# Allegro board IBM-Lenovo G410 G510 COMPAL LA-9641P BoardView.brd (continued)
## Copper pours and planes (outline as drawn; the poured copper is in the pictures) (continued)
B+ on TOP (solid shape): 112.19,29.18 112.19,26.91 112,26.72 110.73,26.72 110.47,26.97 110.47,29.11 110.71,29.35 112.02,29.35
B+ on TOP (solid shape): 178.96,138.74 178.96,133.74 177.59,132.37 177.59,130.35 177.08,129.84 175.05,129.84 174.86,130.03 174.86,132.27 176.21,133.63 176.21,136.54 174.89,137.86 174.89,138.95 175.2,139.26 178.45,139.26
B+ on TOP (solid shape): 192.32,62.08 192.32,60.58 192.17,60.44 191.85,60.44 191.8,60.49 191.8,60.99 191.77,61.02 191.31,61.02 191.29,61 191.29,60.5 191.23,60.44 190.95,60.44 190.9,60.5 190.9,62.09 191.03,62.22 192.18,62.22
B+ on TOP (solid shape): 167.15,177.75 167.15,175.29 166.63,174.77 165.46,174.77 163.77,176.46 148.02,176.46 147.6,176.88 143.45,176.88 143.03,176.46 137.48,176.46 137.34,176.59 127.75,176.59 127.62,176.46 110.86,176.46 110.17,175.77 108.75,175.77 108.32,176.2 108.32,177.97 108.62,178.27 166.63,178.27
B+ on TOP (solid shape): 178.77,162.87 178.77,161.29 179.32,160.74 181.27,160.74 181.38,160.63 181.38,159.95 181.32,159.88 179.91,159.88 179.9,159.89 179.86,159.89 179.62,159.65 179.62,159.36 179.91,159.08 181.35,159.08 181.39,159.04 181.39,158.54 181.26,158.42 180.74,158.42 180.61,158.29 180.61,155.45 180.44,155.29 178.7,155.29 178.58,155.4 177.7,155.4 176.71,156.4 176.71,160.43 176.11,161.03 175.64,161.03 175.39,161.28 175.39,162.88 175.64,163.12 178.52,163.12
B+ on BOTTOM (solid shape): 62.08,3.48 62.08,1.55 61.83,1.29 59.34,1.29 59.18,1.45 59.18,3.46 59.45,3.73 61.84,3.73
B+ on BOTTOM (solid shape): 81.51,136.95 81.51,135.36 79.55,133.39 77.58,133.39 75.07,135.89 75.07,137.02 77.38,139.32 79.14,139.32
B+ on BOTTOM (solid shape): 93.4,4.53 93.4,1.54 93.21,1.36 92.03,1.36 91.84,1.55 91.84,4.56 92.01,4.73 93.19,4.73
B+ on BOTTOM (solid shape): 191.46,8.8 191.46,6.42 191.24,6.21 190.24,6.21 190.05,6.4 190.05,8.8 190.29,9.04 191.23,9.04
B+ on BOTTOM (solid shape): 96.86,153.09 96.85,153.08 96.85,152.64 96.87,152.63 96.87,151.99 96.86,151.99 96.86,150.67 96.68,150.49 95.79,150.49 95.57,150.71 95.57,153.11 95.72,153.26 96.69,153.26
B+ on BOTTOM (solid shape): 181.7,160.42 181.7,159.17 181.69,159.09 181.7,159.02 181.7,156.95 181.45,156.7 176.95,156.7 176.66,156.99 176.66,160.51 176.88,160.73 181.39,160.73
B+ on BOTTOM (solid shape): 167.15,177.75 167.15,175.29 166.63,174.77 165.46,174.77 163.77,176.46 138.6,176.46 137.9,177.16 137.38,177.16 137.37,177.17 127.71,177.17 127.69,177.14 127.17,177.14 126.48,176.46 110.86,176.46 110.17,175.77 108.75,175.77 108.32,176.2 108.32,177.97 108.62,178.27 166.63,178.27
B+ on VCC (solid shape): outline of 12092 points within 57.77,0.88 211.43,178.48
B+ on IN2 (solid shape): outline of 209 points within 194.64,42.94 200.94,79.82
B+ on IN2 (solid shape): outline of 941 points within 76.22,135.91 167.22,178.18
B+_0.95V on TOP (solid shape): 177.77,127.83 177.77,125.78 177.62,125.63 172.57,125.63 172.44,125.75 172.44,127.09 172.54,127.19 174.32,127.19 174.88,127.75 174.88,129.03 175.08,129.22 176.38,129.22
B+_1.5V on BOTTOM (solid shape): 197.44,10.6 197.44,6.71 196.93,6.2 192.47,6.2 192.3,6.37 192.3,9.36 193.59,10.64 197.4,10.64
BATT+ on TOP (solid shape): 176.93,170.39 177.47,170.39 178.29,169.57 179.22,169.57 180.05,168.73 180.05,166.3 179.8,166.04 175.74,166.04 173.04,168.74 170.63,168.74 170.55,168.82 170.55,170.27 170.34,170.48 169.96,170.48 169.74,170.26 169.74,168.75 168.76,167.78 168.76,166.78 168.55,166.57 167.83,166.57 167.73,166.67 167.73,170 167.53,170.2 167.53,171.11 167.96,171.54 175.78,171.54
BATT+ on BOTTOM (solid shape): 178.39,169.57 179.17,169.57 179.31,169.43 179.31,167.6 179.27,167.56 174.61,167.56 174.4,167.77 174.4,170.01 174.62,170.24 177.72,170.24
BOOT1_1_VGA on TOP (solid shape): 183.98,143.15 183.98,142.35 183.89,142.25 181.91,142.25 181.82,142.34 181.82,143.1 181.96,143.23 183.9,143.23
BOOT1_VGA on TOP (solid shape): 185.38,143.13 185.38,141.98 185.93,141.43 185.93,140.3 185.86,140.24 185.78,140.24 185.71,140.3 185.71,141.2 185.55,141.37 185.38,141.37 184.49,142.25 184.49,143.14 184.68,143.33 185.18,143.33
BOOT2_2_VGA on TOP (solid shape): 181.11,137.47 181.11,135.51 180.97,135.36 180.31,135.36 180.15,135.52 180.15,137.47 180.36,137.68 180.9,137.68
BOOT2_VGA on TOP (solid shape): 185.25,136.51 185.25,136.41 184.23,135.39 181.84,135.39 181.72,135.39 181.67,135.45 181.67,136.33 181.74,136.41 182.7,136.41 183.18,135.93 183.63,135.93 184.27,136.57 185.2,136.57
BQ24737VCC on TOP (solid shape): 186.92,165.78 186.92,165.67 186.18,164.93 185.76,164.93 185.61,165.09 185.61,165.58 185.9,165.87 186.82,165.87
BQ24737VCC on BOTTOM (solid shape): 184.58,166.37 184.58,165.6 184.56,165.5 184.58,165.4 184.58,165.24 184.73,165.08 185.32,165.08 185.78,165.54 186.02,165.54 186.14,165.42 186.14,163.48 185.78,163.12 183.86,163.12 183.43,163.55 183.43,166.24 183.59,166.39 183.64,166.4 183.68,166.41 184.53,166.41
BQ24737VDD on TOP (solid shape): 186.18,167.89 186.81,167.89 186.92,167.78 186.92,167.68 186.81,167.58 185.31,167.58 184.39,168.5 183.06,168.5 182.86,168.69 182.86,170.07 183.06,170.26 183.81,170.26
BST_1.05VSP on TOP (solid shape): 101.43,36.15 101.43,33.96 102.02,33.36 102.34,33.36 102.42,33.28 102.42,33.15 102.34,33.08 101.15,33.08 100.36,33.87 100.36,36.1 100.51,36.25 101.33,36.25
BST_1.35V on TOP (solid shape): 37.21,8.41 37.21,7.4 37.05,7.24 36.46,7.24 35.88,7.82 33.91,7.82 33.85,7.88 33.85,8.03 33.88,8.06 35.26,8.06 35.46,8.26 35.67,8.26 35.92,8.51 37.1,8.51
BST_1.35V-1 on TOP (solid shape): 38.54,8.22 38.54,6.52 38.44,6.42 37.54,6.42 37.43,6.54 37.43,8.23 37.56,8.36 38.4,8.36
BST_3V on TOP (solid shape): 65.01,6.95 65.01,5.61 65.01,5.61 65.01,5.14 65.34,4.81 65.43,4.81 65.52,4.71 65.52,3.69 65.44,3.6 64.75,3.6 64.51,3.85 64.51,6.94 64.63,7.06 64.9,7.06
BST_3V_1 on TOP (solid shape): 67.99,4.78 67.99,3.84 67.9,3.76 66.24,3.76 66.2,3.8 66.2,4.78 66.26,4.85 67.92,4.85
BST_5V on TOP (solid shape): 99.97,7.63 99.97,7.08 99.82,6.93 98.75,6.93 98.19,6.37 97.11,6.37 97.02,6.46 97.02,7.04 97.12,7.15 98,7.15 98.15,7.3 98.15,7.62 98.3,7.77 99.82,7.77
BST_5V on BOTTOM (solid shape): 99.99,7.57 99.99,7.33 100.44,6.89 100.44,6.52 100.34,6.43 100.15,6.43 99.4,7.19 99.4,7.6 99.54,7.74 99.82,7.74
BST_5V_1 on TOP (solid shape): 99.59,8.71 99.59,8.01 99.49,7.91 98.17,7.91 98.02,7.76 97.15,7.76 97.08,7.84 97.08,8.75 97.2,8.88 99.43,8.88
BST_CHG on TOP (solid shape): 184.39,168.14 185.15,167.38 186.83,167.38 186.93,167.27 186.93,167.17 186.86,167.1 185.6,167.1 185.59,167.11 185.47,167.12 185.36,167.11 185.35,167.1 184.92,167.1 184.81,167.12 184.7,167.1 183.69,167.1 183.69,167.11 183.28,167 183.26,166.58 183.26,165.51 183.18,165.43 182.25,165.43 182.15,165.53 182.15,165.67 182.15,167.84 182.46,168.14 184.09,168.14
BST_CPU_PHASE1 on BOTTOM (solid shape): 28.2,124.97 28.2,123.88 28.02,123.7 27.37,123.7 26.49,122.82 25.5,122.82 25.44,122.88 25.44,123.02 27.52,125.09 28.08,125.09
BST_CPU_PHASE1-1 on BOTTOM (solid shape): 29.64,124.98 29.64,123.25 29.47,123.07 28.91,123.07 28.78,123.21 28.78,124.96 28.95,125.14 29.48,125.14
BSTA2 on TOP (solid shape): 29.6,94.37 29.6,93.72 29.43,93.55 29.43,92.86 29.38,92.81 28.65,92.81 28.57,92.89 28.57,94.32 28.7,94.46 29.51,94.46
BSTA2_1 on TOP (solid shape): 31.97,94.59 31.97,93.85 31.88,93.75 31.1,93.75 30.91,93.56 30.25,93.56 30.14,93.67 30.14,94.66 30.24,94.76 31.8,94.76
CHASSIS1_GND on TOP (solid shape): 20.8,79.13 20.8,78.27 20.6,78.07 19.56,78.07 19.4,78.22 19.4,79.12 19.55,79.27 20.66,79.27
CHASSIS1_GND on TOP (solid shape): 14.86,80.86 14.86,79.73 14.69,79.56 12.87,79.56 12.77,79.66 12.77,80.86 12.96,81.05 14.67,81.05
CHASSIS1_GND on TOP (solid shape): 21.01,86.32 21.01,85.47 21,85.46 21,83.75 20.8,83.54 19.44,83.54 19.34,83.64 19.34,86.25 19.56,86.47 20.87,86.47
CHASSIS1_GND on TOP (solid shape): 14.11,99.99 14.11,97.63 16.5,95.23 21.76,95.23 23.39,93.61 23.39,88.4 23.11,88.12 20.67,88.12 20.43,88.36 20.43,92.82 19.54,93.71 14.93,93.71 12.04,96.6 12.04,98.83 10.68,100.19 8.8,100.19 8.28,99.67 7.94,99.67 7.78,99.84 7.78,101.26 8.45,101.92 12.17,101.92
CHASSIS1_GND on GND: 15.03,75.85 13.06,77.82 9.45,77.82 9.3,77.67 9.3,77.61 8.04,78.03 7.11,77.07 1.1,77.07 0.57,77.28 0.36,77.81 0.36,80.29 0.57,80.81 1.1,81.03 8.47,81.03 10.59,80.4 9.96,82.51 9.96,96.66 10.59,98.77 8.47,98.14 1,98.14 0.47,98.36 0.26,98.88 0.26,101.11 0.35,101.01 5.2,101.01 5.86,101.67 11.38,101.67 12.3,100.75 12.3,95.4 10.65,93.75 10.65,85.41 11.18,84.88 12.41,84.88 14.08,86.56 14.08,90.38 14.41,90.38 19.92,84.87 19.92,77.05 18.72,75.85
CHG on TOP (solid shape): 169.75,167.63 169.75,166.13 169.95,165.94 170.31,165.94 170.56,166.18 170.56,167.6 170.64,167.69 171.34,167.69 171.53,167.51 171.53,165.25 171.07,164.8 166.55,164.8 166.38,164.97 166.38,166.23 166.56,166.41 168.66,166.41 169.02,166.77 169.02,167.65 169.06,167.7 169.68,167.7
CHG on BOTTOM (solid shape): 172.68,170.82 172.68,165.25 172.19,164.75 166.55,164.75 166.35,164.95 166.35,169.21 168.13,170.99 172.51,170.99
CHG_B+ on TOP (solid shape): 182.02,167.74 182.02,165.72 179.85,163.55 175.12,163.55 174.81,163.23 174.81,160.79 175.01,160.59 176.04,160.59 176.28,160.34 176.28,158.8 176.09,158.61 171.76,158.61 171.38,158.99 171.38,160.45 171.69,160.76 173.03,160.76 173.53,161.26 173.53,166.19 173.6,166.26 174.91,166.26 175.4,165.77 179.98,165.77 180.53,166.32 180.53,167.68 180.64,167.79 181.97,167.79
CHG_B+ on BOTTOM (solid shape): 181.87,165.74 181.87,163.36 181.42,162.91 175.8,162.91 175.2,163.51 175.2,165.66 175.49,165.96 181.66,165.96
CPU_B+ on TOP (solid shape): 75.63,132.46 75.63,131.6 74.57,130.54 73.35,130.54 71.14,132.75 71.14,133.58 72.33,134.77 73.31,134.77
CPU_B+ on TOP (solid shape): 44.7,131.26 44.7,122.4 44.36,122.07 43.62,122.07 40.79,119.24 40.79,114.94 36.11,110.26 36.11,104.92 36.06,104.87 36.13,104.81 36.13,100.58 35.92,100.38 30.63,100.38 30.37,100.12 29.26,100.12 28.8,99.67 28.8,95.73 28.71,95.64 27.72,95.64 26.29,94.21 25.29,94.21 25.22,94.28 25.22,95.79 25.63,96.21 25.63,104.21 26.12,104.7 30.46,104.7 30.84,105.08 30.96,105.08 30.91,105.12 30.91,109.48 38.51,117.07 38.51,120.71 39.98,122.18 39.98,126.6 39.07,127.51 35.72,127.51 33.48,125.27 32.19,125.27 32.04,125.42 32.04,128.8 31.82,129.01 30.27,129.01 29.52,128.27 27.95,128.27 27.79,128.43 27.79,129.42 28.06,129.69 35.58,129.69 37.52,131.63 44.33,131.63
CPU_B+ on BOTTOM (solid shape): 27.41,100.47 27.41,94.54 26.91,94.03 23.92,94.03 23.48,94.47 23.48,100.5 23.67,100.7 27.19,100.7
CPU_B+ on VCC (solid shape): outline of 560 points within 36.62,122.59 74.86,139.64
DH_1.05VSP on TOP (solid shape): 103.29,36.11 103.29,33.53 103.21,33.44 103.07,33.44 102.99,33.52 102.99,34.69 102.76,34.93 102.76,36.11 102.85,36.2 103.19,36.2
DH_1.05VSP on TOP (solid shape): 110.38,33.45 110.45,33.45 110.64,33.26 110.64,32.85 110.64,32.84 110.64,32.29 110.36,32.01 109.02,32.01 108.89,32.14 108.89,32.15 108.71,32.33 108.71,33.26 108.91,33.45 110.37,33.45
DH_1.05VSP on IN1 (solid shape): 103.38,37.24 103.38,34.86 103.22,34.7 102.85,34.7 102.58,34.97 102.58,37.28 102.76,37.46 103.16,37.46
DH_1.05VSP on IN1 (solid shape): 110.36,33.07 110.36,32.13 110.19,31.97 109.2,31.97 109.05,32.11 109.05,32.99 109.36,33.3 110.12,33.3
DH_CHG on TOP (solid shape): 176.75,156 176.75,153.67 176.47,153.4 175.66,153.4 175.43,153.63 175.43,156.1 175.6,156.28 176.46,156.28
DH_CHG on TOP (solid shape): 183.66,164.93 184.37,164.93 184.41,164.9 184.41,164.26 184.38,164.23 183.43,164.23 183.32,164.35 183.32,164.72 183.22,164.82 182.25,164.82 182.17,164.91 182.17,165.18 182.26,165.28 183.32,165.28
DH_CHG on IN2 (solid shape): 177.83,155.66 177.83,155.02 177.59,154.78 175.88,154.78 175.56,155.11 175.56,155.89 175.83,156.15 177.33,156.15
DH_CHG on IN2 (solid shape): 183.3,165.17 183.3,164.04 183.13,163.86 182.27,163.86 182.1,164.03 182.1,165.12 182.28,165.3 183.18,165.3
DH_CHG-1 on TOP (solid shape): 185.72,166.87 186.82,166.87 186.92,166.78 186.92,166.68 186.84,166.6 185.57,166.6 185.42,166.46 185.04,166.46 184.44,165.86 184.44,165.69 184.39,165.64 183.54,165.64 183.5,165.68 183.5,166.29 183.55,166.33 183.7,166.33 184.34,166.97 185.62,166.97
DISCHG_G on TOP (solid shape): 180.75,162.69 180.75,161.75 180.19,161.19 179.48,161.19 179.28,161.39 179.28,162.94 179.47,163.13 180.32,163.13
DL_1.05VSP on TOP (solid shape): 118.3,44.19 118.3,44.18 118.41,44.07 118.41,42.53 118.28,42.4 116.64,42.4 116.37,42.67 116.37,43.09 117.68,44.4 118.08,44.4
DL_1.05VSP on TOP (solid shape): 104.09,35.85 104.09,34.96 103.79,34.65 103.79,33.54 103.7,33.45 103.59,33.45 103.5,33.54 103.5,34.14 103.51,34.15 103.51,35.83 103.68,36 103.95,36
DL_1.05VSP on IN2 (solid shape): 118.17,44.27 118.17,43.3 117.21,42.34 115.86,42.34 115.58,42.63 115.58,43.52 116.48,44.42 118.02,44.42
DL_1.05VSP on IN2 (solid shape): 105.56,37.27 105.56,36.36 105.36,36.15 104.62,36.15 104.15,35.68 104.15,34.96 103.98,34.79 103.7,34.79 103.51,34.98 103.51,36.95 103.91,37.36 105.47,37.36
DL_CHG on TOP (solid shape): 166.59,163.55 166.59,161.18 166.3,160.89 166.11,160.89 165.76,161.23 165.76,162.17 165.3,162.64 165.3,163.58 165.46,163.74 166.4,163.74
DL_CHG on TOP (solid shape): 187.25,168.88 187.25,168 187.16,167.92 187.07,167.92 186.7,168.29 186.27,168.29 186.12,168.44 186.12,169.36 186.24,169.48 186.65,169.48
DL_CHG on IN2 (solid shape): 167.01,163.09 167.01,161.98 166.82,161.79 166.13,161.79 165.37,162.55 165.37,163.57 165.56,163.76 166.33,163.76
DL_CHG on IN2 (solid shape): 186.7,169.37 186.7,168.49 186.49,168.27 186.29,168.27 186.11,168.44 185.11,168.44 184.91,168.64 184.91,169.41 185.07,169.57 186.51,169.57
ECAGND on TOP (solid shape): 158.46,88.89 158.46,88.38 158.46,88.38 158.46,88.32 159.2,87.59 159.2,87.08 158.83,86.71 157.73,86.71 157.51,86.92 157.51,87.65 157.01,88.15 156.95,88.15 156.69,88.41 156.69,89.01 156.79,89.11 158.24,89.11
ENLDO_3V5V on TOP (solid shape): 112.56,4.6 112.56,2.99 112.35,2.78 110.83,2.78 110.66,2.96 110.66,4.64 110.75,4.73 112.43,4.73
HG1 on TOP (solid shape): 39.25,122.87 39.25,122.25 38.7,121.7 37.42,121.7 37.23,121.88 37.23,122.06 38.22,123.05 39.08,123.05
HG1 on BOTTOM (solid shape): 28.47,123.39 28.47,123.11 28.35,122.99 27.35,122.99 26.78,122.42 25.5,122.42 25.44,122.49 25.44,122.57 25.49,122.63 26.52,122.63 27.39,123.49 27.39,123.49 27.43,123.53 28.33,123.53
HG1 on IN2 (solid shape): 38.46,123.99 38.46,121.84 38.27,121.65 37.52,121.65 37.23,121.93 37.23,122.62 36.86,122.99 27.4,122.99 27.23,123.16 27.23,123.37 27.38,123.51 30.74,123.51 31.34,124.11 38.34,124.11
HG2 on TOP (solid shape): 38.22,105.39 38.22,104.44 38.04,104.27 37.11,104.27 36.62,104.76 36.62,105.78 36.79,105.95 37.66,105.95
HG2 on TOP (solid shape): 32.94,93.39 32.94,93.13 32.81,92.99 31.94,92.99 31.77,92.83 30.88,92.83 30.82,92.89 30.82,93.01 30.9,93.09 31.48,93.09 31.93,93.54 32.8,93.54
HG2 on IN1 (solid shape): 37.89,105.78 37.89,104.06 37.54,103.71 36.84,103.71 36.56,104 36.56,105.71 36.75,105.9 37.76,105.9
HG2 on IN1 (solid shape): 34.03,94.24 34.03,93.35 33.65,92.97 31.94,92.97 31.74,93.16 31.74,93.79 31.87,93.92 32.7,93.92 33.21,94.43 33.84,94.43
HG3 on TOP (solid shape): 26.48,106.71 26.48,105.7 26.26,105.48 25.24,105.48 25.1,105.62 25.1,106.76 25.22,106.88 26.31,106.88
HG3 on BOTTOM (solid shape): 26.52,119.74 26.52,119.43 26.82,119.13 26.82,119.13 27.26,118.68 28.36,118.68 28.49,118.55 28.49,118.3 28.31,118.13 26.91,118.13 25.44,119.6 25.44,119.77 25.51,119.83 26.43,119.83
HG3 on IN2 (solid shape): 26.85,106.69 26.85,105.81 26.64,105.6 25.16,105.6 25.04,105.71 25.04,106.63 25.2,106.78 26.76,106.78
HG3 on IN2 (solid shape): 29.49,117.95 29.49,117.44 29.28,117.23 27.85,117.23 27.68,117.4 27.71,117.44 27.75,117.84 27.38,118.02 27.3,118.04 27.27,118.12 27.27,118.48 27.45,118.66 28.78,118.66
HGNDA on TOP (solid shape): 151.15,50.47 152,50.47 152.12,50.36 152.12,50.05 152.01,49.94 150.08,49.94 149.98,50.03 149.98,50.67 150.02,50.71 150.91,50.71
HGNDA on BOTTOM (solid shape): 24.34,16.71 24.34,15.93 24.2,15.8 19.74,15.8 19.21,15.26 17.2,15.26 17.02,15.44 17.02,16.19 17.69,16.86 24.19,16.86
HGNDA on BOTTOM (solid shape): 120.61,23.94 120.61,23.54 120.6,23.54 119.15,22.08 118.83,22.08 118.52,22.39 118.52,23.1 119.63,24.21 120.35,24.21
HGNDA on IN1 (solid shape): 121.52,24.69 121.52,24.28 121.51,24.28 120.06,22.83 119.74,22.83 119.43,23.14 119.43,23.85 120.54,24.96 121.26,24.96
HGNDA on IN1 (solid shape): outline of 310 points within 145.11,49.95 152.36,56.57
HGNDA on IN2 (solid shape): 17.63,16.23 17.63,15.43 17.62,15.41 17.62,15.19 17.44,15.01 16.01,15.01 15.86,15.15 15.86,16.28 16.02,16.43 17.43,16.43
HGNDB on TOP (solid shape): 152.25,49.57 152.25,49.19 152.17,49.11 150.57,49.11 150.53,49.07 150.04,49.07 150.01,49.1 150.01,49.65 150.03,49.68 152.15,49.68
HGNDB on BOTTOM (solid shape): 19.88,13.88 19.89,13.88 19.98,13.79 24.22,13.79 24.49,13.53 24.49,13.03 24.26,12.8 17.61,12.8 17,13.41 17,14.22 17.26,14.48 19.29,14.48
HGNDB on BOTTOM (solid shape): 121.34,22.31 121.34,21.9 119.87,20.43 119.36,20.43 119.23,20.56 119.23,21.19 120.65,22.61 121.04,22.61
HGNDB on IN1 (solid shape): 17.54,14.27 17.54,13.47 17.35,13.28 15.75,13.28 15.55,13.48 15.55,14.16 15.81,14.43 17.37,14.43
HGNDB on IN1 (solid shape): 122.22,23.41 122.22,22.99 120.75,21.52 120.24,21.52 120.11,21.65 120.11,22.29 121.53,23.7 121.92,23.7
HGNDB on IN1 (solid shape): 152.3,49.44 152.3,48.94 151.44,48.08 149.74,48.08 149.44,48.38 149.44,49.36 149.72,49.64 152.09,49.64
LG1 on TOP (solid shape): 29.85,121.86 29.85,121.1 30.09,120.85 31.2,120.85 31.37,120.69 31.37,120.4 31.16,120.19 29.58,120.19 28.61,121.16 28.61,121.96 28.76,122.11 29.6,122.11
LG1 on BOTTOM (solid shape): 29.88,121.96 29.88,121.58 29.7,121.4 28.73,121.4 28.51,121.62 25.5,121.62 25.44,121.68 25.44,121.77 25.5,121.83 27.51,121.83 27.57,121.89 27.57,121.89 27.76,122.07 29.76,122.07
LG2 on TOP (solid shape): 37.76,95.11 37.76,93.77 37.51,93.52 36.37,93.52 36.18,93.71 36.18,95.19 36.43,95.44 37.43,95.44
LG2 on TOP (solid shape): 31.92,91.35 33.61,91.35 33.88,91.08 33.88,90.67 33.54,90.33 31.93,90.33 31.73,90.53 31.73,90.97 31.38,91.32 30.89,91.32 30.82,91.4 30.82,91.51 30.9,91.58 31.68,91.58
LG3 on TOP (solid shape): 25.32,101.9 25.32,100.82 24.68,100.19 23.92,100.19 23.76,100.35 23.76,101.31 24.02,101.57 24.41,101.57 24.94,102.09 25.13,102.09
LG3 on BOTTOM (solid shape): 27.33,120.1 28.32,120.1 28.46,119.96 28.46,119.71 28.31,119.56 27.44,119.56 27.26,119.75 27.26,119.82 26.65,120.42 25.5,120.42 25.44,120.48 25.44,120.57 25.49,120.63 26.81,120.63
LG3 on IN2 (solid shape): 26.33,101.39 26.33,100.6 25.98,100.24 25.39,100.24 24.72,100.91 24.72,101.87 24.94,102.09 25.64,102.09
LG3 on IN2 (solid shape): 29.81,119.89 29.81,119.29 29.56,119.04 29.11,119.04 28.56,119.59 27.41,119.59 27.26,119.74 27.26,119.97 27.39,120.1 29.59,120.1
LG_1.35V on TOP (solid shape): 34.19,6.42 34.25,6.42 34.43,6.24 34.43,5.39 34.3,5.26 33.97,5.26 33.83,5.4 33.83,5.66 33.44,6.05 33.44,6.79 33.47,6.83 33.79,6.83
LG_1.35V on BOTTOM (solid shape): 38.45,7.1 38.45,6.79 38.28,6.62 37.15,6.62 36.3,5.76 34.79,5.76 34.27,5.24 34.02,5.24 33.79,5.47 33.79,5.69 33.79,5.69 33.79,6.34 34.16,6.72 36.03,6.72 36.6,7.29 38.25,7.29
LGATE1_VGA on TOP (solid shape): 184.1,139.36 185.19,139.36 185.24,139.3 185.24,139.21 185.18,139.15 183.89,139.15 183.7,139.34 182.51,139.34 182.41,139.45 182.41,139.75 182.52,139.86 183.6,139.86
LGATE1_VGA on BOTTOM (solid shape): 172.48,145.22 172.48,144.79 172.31,144.61 171.74,144.61 171.35,144.23 170.39,144.23 170.24,144.38 170.24,145.27 170.41,145.45 172.25,145.45
LGATE1_VGA on IN2 (solid shape): 173.02,145.18 173.02,144.39 172.73,144.1 170.41,144.1 170.22,144.29 170.22,145.28 170.35,145.41 172.79,145.41
LGATE1_VGA on IN2 (solid shape): 181.97,139.88 182.57,139.88 182.66,139.87 182.75,139.88 183.43,139.88 183.61,139.7 183.61,139.5 183.45,139.34 180.57,139.34 180.3,139.6 180.3,140.24 180.66,140.6 181.26,140.6
LGATE2_VGA on TOP (solid shape): 183.99,138.17 185.18,138.17 185.24,138.1 185.24,138.01 185.19,137.96 182.63,137.96 182.49,138.1 182.49,138.36 182.61,138.48 183.67,138.48
LGATE2_VGA on BOTTOM (solid shape): 171.48,137.33 172.09,137.33 172.36,137.06 172.36,136.71 172.06,136.41 170.9,136.41 170.75,136.56 170.75,137.45 170.94,137.64 171.18,137.64
LGATE2_VGA on IN2 (solid shape): 172.97,137.63 172.97,136.68 172.73,136.45 170.92,136.45 170.78,136.59 170.78,137.67 170.95,137.84 172.75,137.84
LGATE2_VGA on IN2 (solid shape): 182.68,138.52 182.77,138.53 183.29,138.53 183.34,138.53 183.55,138.53 183.7,138.37 183.7,138.11 183.56,137.98 182.43,137.98 181.85,137.4 180.62,137.4 180.47,137.54 180.47,138.53 182.59,138.53
LX_0.95V on TOP (solid shape): 171.44,127.75 171.44,126.67 171.39,126.62 170.39,126.62 169.39,125.62 168.45,125.62 168.26,125.8 168.26,127.38 168.69,127.8 171.39,127.8
LX_0.95V on BOTTOM (solid shape): 168.47,129.99 168.47,129.08 168.73,128.82 170.11,128.82 170.29,128.64 170.29,126.34 169.44,125.49 169.44,123.63 169.19,123.37 166.5,123.37 165.92,123.96 165.92,129.91 166.16,130.15 168.32,130.15
LX_1.5V on TOP (solid shape): outline of 89 points within 197.41,6.97 206.49,11.44
LX_1.5V on BOTTOM (solid shape): 199.66,10.42 200.12,10.42 200.32,10.61 202.32,10.61 202.53,10.4 202.53,7.37 202.23,7.07 199.95,7.07 199.79,7.23 199.79,9.31 199.66,9.44 198.53,9.44 198.51,9.46 198.51,10.62 198.52,10.63 199.44,10.63
LX_1.05VSP on TOP (solid shape): 102.6,36.27 102.6,35.43 102.53,35.35 102.53,34.95 102.79,34.69 102.79,33.53 102.7,33.44 102.59,33.44 101.66,34.38 101.66,36.18 101.79,36.31 102.56,36.31
LX_1.05VSP on TOP (solid shape): 113.35,45.55 113.35,43.7 113.78,43.28 113.78,39.07 112.15,37.44 112.15,34.43 111.69,33.97 108.58,33.97 108.39,34.16 108.39,45.19 109.23,46.02 112.88,46.02
LX_1.05VSP on BOTTOM (solid shape): 114.72,40.66 114.72,36.31 114.03,35.61 109.2,35.61 108.38,36.43 108.38,40.72 108.74,41.08 114.3,41.08
LX_1.05VSP on IN2 (solid shape): 102.58,35.27 102.58,34.32 102.28,34.02 101.84,34.02 101.62,34.24 101.62,35.33 101.85,35.56 102.28,35.56
LX_1.05VSP on IN2 (solid shape): 109.87,38.78 109.87,38.3 109.7,38.12 108.55,38.12 108.42,38.26 108.42,38.79 108.57,38.95 109.71,38.95
LX_1.35V on TOP (solid shape): 45.83,10.62 45.83,5.41 45.36,4.95 37.58,4.95 37.16,5.36 35.52,5.36 33.84,7.05 33.84,7.2 33.89,7.25 34.73,7.25 34.75,7.23 34.75,7.03 35.36,6.42 37.28,6.42 37.47,6.22 38.55,6.22 39.66,7.33 39.66,10.55 40.07,10.96 45.49,10.96
LX_1.35V on BOTTOM (solid shape): 45.97,10.73 45.97,7.08 46.93,6.12 49.61,6.12 49.89,5.83 49.89,3.03 49.45,2.59 46.92,2.59 46.66,2.85 46.66,4.73 45.82,5.57 44.32,5.57 43.76,5.01 43.76,2.83 43.5,2.57 39.37,2.57 38.97,2.97 38.97,10.72 39.62,11.36 45.33,11.36
LX_3V on TOP (solid shape): 73.76,13.52 73.76,4.69 72.63,3.56 68.93,3.56 68.65,3.84 68.65,5.58 69.39,6.32 69.39,7.59 69.19,7.8 66.63,7.8 66.58,7.84 66.58,8.94 68.25,8.94 71.28,11.97 71.28,13.6 71.61,13.93 73.35,13.93
LX_5V on TOP (solid shape): 106.59,6.55 106.59,5.18 106.36,4.95 103.98,4.95 103.86,5.08 103.86,6.69 104.01,6.84 106.29,6.84
LX_5V on BOTTOM (solid shape): 108.75,11.27 108.75,6.73 106.52,4.51 102.01,4.51 102.01,5.66 102.05,5.7 103.27,5.7 103.43,5.86 103.43,6.65 103.48,6.68 103.53,6.71 103.57,6.75 103.61,6.79 103.64,6.84 103.66,6.89 103.67,6.95 103.67,7.01 103.67,7.06 103.66,7.12 103.64,7.17 103.61,7.22 103.57,7.26 103.53,7.3 103.48,7.33 103.43,7.36 103.43,7.91 102.28,9.07 102.28,10.96 102.42,10.96 102.42,10.91 102.43,10.85 102.44,10.8 102.47,10.75 102.5,10.71 102.53,10.67 102.57,10.64 102.62,10.61 102.67,10.59 102.72,10.58 102.78,10.58 102.83,10.58 102.88,10.59 102.93,10.61 102.98,10.64 103.02,10.67 103.05,10.71 103.08,10.75 103.11,10.8 103.12,10.85 103.13,10.91 103.13,10.96 103.12,11.01 103.11,11.06 103.08,11.11 103.05,11.15 103.02,11.19 102.98,11.23 102.93,11.25 102.88,11.27 102.83,11.28 102.78,11.29 102.72,11.28 102.67,11.27 102.62,11.25 102.57,11.23 102.53,11.19 102.5,11.15 102.47,11.11 102.44,11.06 102.43,11.01 102.42,10.96 102.28,10.96 102.28,11.49 102.87,12.08 107.93,12.08
LX_CHG on TOP (solid shape): 174.96,157.24 174.96,153.58 174.66,153.28 167.93,153.28 165.77,155.44 165.77,157.54 166,157.77 174.43,157.77
LX_CHG on TOP (solid shape): 186.91,166.28 186.91,166.19 186.82,166.1 185.86,166.1 185.45,165.69 185.45,163.26 184.91,162.72 183.65,162.72 183.59,162.79 183.59,163.66 183.67,163.74 184.4,163.74 184.57,163.9 184.57,165.72 185.13,166.28 185.47,166.28 185.56,166.37 186.82,166.37
LX_CHG on BOTTOM (solid shape): 173.13,161.18 173.13,153.92 172.34,153.14 170.94,153.14 170.29,153.78 170.29,155.79 169.94,156.15 169.91,156.15 167.82,158.25 167.82,161.36 168.35,161.89 172.42,161.89
LX_CHG on IN1 (solid shape): 185.61,166.12 185.61,165.8 184.91,165.09 183.62,165.09 183.41,165.3 183.41,166.01 183.71,166.3 185.43,166.3
LX_CHG on IN1 (solid shape): 173.72,158.05 173.72,156.27 171.24,153.78 170.27,153.78 170.03,154.02 170.03,156.82 171.43,158.22 173.56,158.22
MCT on BOTTOM (solid shape): 18.31,82.74 18.31,82.48 18.03,82.2 16.45,82.2 15.98,81.73 15.98,80.93 15.78,80.73 15.19,80.73 15.06,80.86 15.06,82.72 15.36,83.01 18.04,83.01
MCT on IN1 (solid shape): 16.15,83.86 16.15,82.05 15.99,81.89 15.38,81.89 15.21,82.05 15.21,83.85 15.34,83.97 16.04,83.97
P2 on TOP (solid shape): 190.95,160.78 190.95,157.22 190.65,156.91 187.64,156.91 187.34,157.21 187.34,161.03 187.6,161.3 190.44,161.3
P2 on BOTTOM (solid shape): 189.03,162.24 189.03,159.29 189.36,158.96 189.98,158.96 190.39,158.56 190.39,157.26 190.05,156.92 187.63,156.92 187.31,157.24 187.31,157.64 185.8,159.15 183.96,159.15 183.64,159.47 183.64,162.42 183.73,162.51 188.77,162.51
P3 on TOP (solid shape): 186.02,162.27 186.02,156.6 185.83,156.41 184.21,156.41 182.43,158.18 182.43,158.98 182.53,159.08 183.96,159.08 184.19,159.3 184.19,159.65 183.94,159.89 182.48,159.89 182.43,159.95 182.43,162.09 182.84,162.5 185.79,162.5
P3 on BOTTOM (solid shape): 186.96,157.56 186.96,156.81 187.38,156.39 190.5,156.39 190.71,156.19 190.71,154.19 190.51,153.99 184.86,153.99 184.74,154.12 184.74,154.14 184.7,154.36 184.53,154.52 184.5,154.53 184.5,156.23 182.7,158.04 182.7,158.57 182.95,158.82 185.71,158.82
PHASE1_VGA on TOP (solid shape): 183.39,141.56 183.4,141.54 183.48,141.37 183.65,141.28 183.67,141.28 184.79,140.16 185.19,140.16 185.24,140.11 185.24,140.01 185.19,139.95 184.28,139.95 183.24,141 181.94,141 181.84,141.1 181.84,141.74 182,141.9 183.06,141.9
PHASE2_VGA on TOP (solid shape): 182.39,137.55 182.39,137.27 182.54,137.12 183.73,137.12 183.97,137.36 185.19,137.36 185.24,137.3 185.24,137.21 185.19,137.16 184.77,137.16 184.76,137.16 184.12,137.16 183.74,136.78 183.18,136.78 182.99,136.59 181.76,136.59 181.69,136.66 181.69,137.55 181.73,137.6 182.35,137.6
PS_0 on TOP (solid shape): 147.14,126.83 147.16,126.77 147.19,126.73 147.19,124.11 147.05,123.96 146.58,123.96 146.46,124.08 146.46,124.75 146.21,125 145.72,125 145.61,125.11 145.61,125.72 145.6,125.73 145.6,126.61 146.03,127.05 146.92,127.05
SNB_0.95V on BOTTOM (solid shape): 173.25,125.22 173.25,123.69 173,123.44 171.04,123.44 170.79,123.69 170.79,125.29 170.96,125.46 173.02,125.46
SNB_1.5V on BOTTOM (solid shape): 205.92,10.4 205.92,8.76 205.66,8.5 203.28,8.5 202.95,8.83 202.95,10.34 203.16,10.56 205.76,10.56
SNUB1_VGA on TOP (solid shape): 171.62,149.55 171.62,148.43 171.29,148.09 168.95,148.09 168.7,148.34 168.7,149.28 169.13,149.72 171.46,149.72
SNUB2_VGA on TOP (solid shape): 170.5,136.17 170.5,135.28 170.28,135.06 170.03,135.06 169.91,134.93 169.91,134.12 169.82,134.03 168.73,134.03 168.56,134.19 168.56,136.15 168.79,136.37 170.29,136.37
SNUB_CPU1 on BOTTOM (solid shape): 30.87,116.32 31.82,116.32 31.99,116.15 31.99,114.98 31.8,114.79 29.13,114.79 28.87,115.05 28.87,117.28 29.01,117.42 29.76,117.42
SNUB_CPU2 on BOTTOM (solid shape): 39.14,97.46 39.14,95.83 38.96,95.66 36.48,95.66 36.34,95.8 36.34,97.38 36.62,97.65 38.94,97.65
SNUB_CPU3 on TOP (solid shape): 19.1,98.47 19.1,97.52 19.04,97.46 18.22,97.46 17.88,97.11 17.88,96.14 17.72,95.99 17.26,95.99 17,96.25 17,98.47 17.16,98.63 18.94,98.63
SW1 on TOP (solid shape): 39.31,126.68 39.31,123.67 39.15,123.51 37.35,123.51 36.74,122.89 36.74,120.14 36.24,119.65 36.24,117.58 35.17,116.51 32.37,116.51 32.03,116.84 32.03,124.28 32.14,124.38 34.51,124.38 36.27,126.14 37.81,126.14 37.97,126.31 37.97,126.68 38.1,126.81 39.18,126.81
SW1 on BOTTOM (solid shape): 35.04,125.6 35.04,123.91 35.02,123.89 35.02,122.21 34.97,122.16 31.99,122.16 31.92,122.09 31.9,122.09 31.9,122.08 31.86,122.03 31.86,121.33 31.92,121.27 35.83,121.27 36.2,120.9 36.2,117.53 35.12,116.44 31.1,116.44 29.76,117.78 29.76,120.7 30.49,121.42 30.49,121.94 30.21,122.22 27.72,122.22 27.52,122.02 25.5,122.02 25.44,122.08 25.44,122.16 25.5,122.23 26.85,122.23 27.4,122.78 30.15,122.78 30.49,123.13 30.49,125.47 30.85,125.82 34.81,125.82
SW1_VGA on TOP (solid shape): 171.74,146.72 171.74,146.2 171.22,145.68 168.89,145.68 168.71,145.86 168.71,146.97 168.9,147.16 171.29,147.16
SW1_VGA on BOTTOM (solid shape): 171.76,149.51 172.43,149.51 172.51,149.42 172.51,146.13 172.29,145.9 166.35,145.9 166.23,146.03 166.23,147.32 166.34,147.43 168.72,147.43 168.79,147.5 168.79,148.26 168.75,148.3 166.36,148.3 166.25,148.41 166.25,149.96 166.43,150.14 171.13,150.14
SW2 on TOP (solid shape): 43.23,103.68 43.23,94.54 43.1,94.41 38.78,94.41 38.4,94.79 38.4,99.13 36.85,100.68 36.85,103.33 37.15,103.64 38.57,103.64 39.12,104.19 42.72,104.19
SW2 on TOP (solid shape): 33.73,94.25 33.73,92.47 33.48,92.22 31.73,92.22 31.62,92.33 31.32,92.33 31.32,92.33 30.9,92.33 30.82,92.4 30.82,92.51 30.89,92.58 31.84,92.58 32.06,92.8 32.98,92.8 33.14,92.96 33.14,93.55 32.97,93.72 32.36,93.72 32.27,93.81 32.27,94.52 32.28,94.54 33.44,94.54
SW2 on BOTTOM (solid shape): 37.89,104.8 37.89,101.76 37.99,101.66 38.69,101.66 38.76,101.73 38.76,104.65 38.98,104.87 42.48,104.87 43.03,104.32 43.03,93.9 42.34,93.2 34.7,93.2 33.73,92.23 31.98,92.23 31.9,92.31 31.9,92.76 31.98,92.84 33.47,92.84 34.37,93.74 38.66,93.74 40.57,95.65 40.57,97.96 39.84,98.68 37.2,98.68 35.92,99.96 35.92,104.81 36.05,104.94 37.75,104.94
SW2_VGA on TOP (solid shape): 170.89,138.67 170.89,138.66 171.06,138.48 171.06,138.24 170.63,137.8 168.56,137.8 168.49,137.88 168.49,138.78 168.61,138.91 170.64,138.91
SW2_VGA on BOTTOM (solid shape): 172.34,141.1 172.34,138.04 172.19,137.89 170.94,137.89 170.55,137.5 170.55,134.04 170.07,133.55 166.25,133.55 166.12,133.68 166.12,134.97 166.24,135.08 168.61,135.08 168.68,135.15 168.68,135.91 168.64,135.95 166.25,135.95 166.15,136.06 166.15,140.74 166.85,141.44 171.99,141.44
SW3 on TOP (solid shape): 30.28,108.94 30.28,105.66 30.03,105.4 27.3,105.4 27,105.71 27,106.83 26.58,107.26 25.18,107.26 24.83,106.91 24.83,102.54 24.53,102.25 20.14,102.25 19.03,101.14 19.03,100.06 18.9,99.93 17.44,99.93 17.25,100.12 17.25,109 17.84,109.59 29.64,109.59
SW3 on BOTTOM (solid shape): 27.11,119.76 27.11,119.68 27.39,119.39 28.31,119.39 28.47,119.24 28.47,118.96 28.34,118.83 27.38,118.83 26.75,119.46 26.75,119.75 26.48,120.02 25.49,120.02 25.43,120.07 25.43,120.17 25.5,120.24 26.64,120.24
SW3 on BOTTOM (solid shape): 22.92,110.26 22.92,108.81 22.56,108.45 18.14,108.45 18.07,108.39 18.07,107.75 18.13,107.69 18.14,107.68 23.6,107.68 24.1,107.17 24.1,104.41 24.09,104.39 24.09,102.3 23.11,101.32 17.61,101.32 17.34,101.59 17.34,110.22 17.72,110.6 22.58,110.6
SW3 on IN1 (solid shape): 22.74,110.7 22.74,109.08 22.53,108.87 21.7,108.87 21.54,109.04 21.54,110.68 21.67,110.82 22.62,110.82
SW3 on IN1 (solid shape): 29.06,119.37 29.53,119.37 29.84,119.06 29.84,118.35 29.61,118.12 29.12,118.12 28.41,118.82 27.47,118.82 27.28,119.01 27.28,119.21 27.44,119.37 29.06,119.37
TL_ENVDD on TOP (solid shape): 88.86,126.68 88.86,126.46 88.7,126.3 88.63,126.3 88.34,126.3 88.06,126.02 87.7,126.02 87.19,126.53 87.19,126.82 87.27,126.9 88.65,126.9
TL_ENVDD on BOTTOM (solid shape): 91.28,143.18 91.28,142.82 91.41,142.69 92.88,142.69 92.98,142.6 92.98,141.75 92.55,141.32 92.55,141.01 92.38,140.84 91.78,140.84 91.63,140.69 91.63,139.25 91.97,138.91 93.33,138.91 93.62,138.62 93.62,137.74 93.44,137.56 90.56,137.56 89.93,138.19 89.93,143.41 90.12,143.59 90.87,143.59
TL_ENVDD on IN1 (solid shape): 94.82,138.69 94.82,136.09 94.37,135.64 92.95,135.64 92.51,136.08 92.51,138.68 92.79,138.97 94.54,138.97
TL_ENVDD on IN1 (solid shape): outline of 100 points within 87.19,125.29 94.37,127.49
UG_1.35V on TOP (solid shape): 36.1,7.32 36.1,7.07 35.95,6.92 35.09,6.92 34.95,7.07 34.95,7.27 34.79,7.43 33.89,7.43 33.85,7.46 33.85,7.62 33.89,7.66 35.76,7.66
UG_1.35V on BOTTOM (solid shape): 48.03,7.35 49.58,7.35 49.82,7.11 49.82,6.78 49.6,6.57 48.31,6.57 48.3,6.57 47.08,6.57 46.28,7.38 46.28,8.42 46.47,8.61 46.77,8.61
UG_1.35V on IN2 (solid shape): 36.79,8.39 36.79,7.55 36.16,6.93 35.06,6.93 34.84,7.15 34.84,7.77 35.59,8.51 36.67,8.51
UG_1.35V on IN2 (solid shape): 47.07,8.43 47.07,6.13 46.84,5.9 45.96,5.9 45.69,6.17 45.69,6.79 46.12,7.22 46.12,8.44 46.31,8.63 46.88,8.63
UGATE1_VGA on TOP (solid shape): 185.07,141.26 185.31,141.26 185.33,141.24 185.46,141.24 185.52,141.18 185.52,140.28 185.46,140.22 185.38,140.22 185.31,140.29 185.31,140.54 184.98,140.87 184.63,140.87 183.96,141.55 183.95,141.61 183.94,141.66 183.94,141.79 184.11,141.96 184.37,141.96
UGATE2_VGA on TOP (solid shape): 185.25,136.9 185.25,136.83 185.17,136.76 184.23,136.76 183.59,136.12 183.27,136.12 183.16,136.24 183.16,136.57 183.24,136.65 183.79,136.65 184.11,136.96 185.18,136.96
VMB on TOP (solid shape): 181.08,173.91 181.08,170.94 180.8,170.66 177.01,170.66 176.66,171 176.66,174 176.92,174.26 180.73,174.26
VMB on BOTTOM (solid shape): 183.53,173.9 183.53,167.81 183.22,167.5 180.3,167.5 180.14,167.65 180.14,169.28 180.2,169.47 180.14,169.65 180.14,170.58 179.01,171.71 179.01,174.06 179.27,174.31 183.11,174.31
VMB2 on TOP (solid shape): 178.46,179.02 178.46,175.41 177.98,174.93 174.84,174.93 174.48,175.28 174.48,178.79 175.29,179.6 177.88,179.6
VMB2 on BOTTOM (solid shape): 178.73,175.88 178.73,170.94 178.26,170.47 175.09,170.47 174.69,170.86 174.69,175.23 174.19,175.95 174.19,176.61 174.52,176.93 177.68,176.93
VMB2 on IN1 (solid shape): outline of 1193 points within 174.11,169.95 195.55,182.95
VMB2 on VCC: 174.26,175.46 174.26,179.16 174.59,179.68 174.75,180.28 174.77,180.29 174.77,180.92 176.21,180.92 178.63,183.34 207.48,183.34 207.48,180.29 207.5,180.28 207.83,179.37 208.54,178.73 208.54,178.4 200.5,170.36 180.47,170.36 175.66,175.16 174.56,175.16
N14561712 on TOP (solid shape): 183.18,162.91 183.02,162.74 182.22,162.74 182.14,162.82 182.14,164.55 182.25,164.67 183.18,164.67
N14568985 on BOTTOM (solid shape): 20.18,123.58 21.1,123.58 21.57,123.11 21.57,122.9 21.48,122.81 19.68,122.81 19.36,123.12 19.36,123.12 18.36,124.13 17.75,124.13 17.72,124.15 17.72,124.79 17.75,124.81 18.94,124.81
N14599537 on TOP (solid shape): 116.76,45.77 116.76,44.31 116.39,43.94 114.42,43.94 114.2,44.16 114.2,45.59 114.46,45.84 116.68,45.84
N16792231 on TOP (solid shape): 32.05,6.8 32.05,6.04 31.05,5.05 31.05,2.95 30.9,2.81 29.2,2.81 29.04,2.97 29.04,3.89 29.04,3.89 29.04,4.84 29.17,4.96 30.11,4.96 31.84,6.69 31.84,6.8 31.88,6.84 32,6.84
N17005206 on TOP (solid shape): 200.31,28.74 200.31,28.03 200.11,27.82 199.27,27.82 198.65,27.2 198.14,27.2 197.9,27.44 197.9,28.06 198.66,28.83 200.22,28.83
N17017158 on TOP (solid shape): 196.74,83.22 196.74,80.31 196.51,80.08 195.88,80.08 195.77,80.2 195.77,83.19 195.88,83.31 196.65,83.31
N17017351 on TOP (solid shape): 194.48,79.8 194.48,79.35 194.39,79.26 192.82,79.26 192.76,79.32 192.76,79.8 192.84,79.89 194.39,79.89
N17242889 on BOTTOM (solid shape): 112.18,17.29 112.18,16.3 112.03,16.15 110.15,16.15 110.08,16.22 110.08,17.27 110.2,17.39 112.09,17.39
N17243787 on TOP (solid shape): 37.55,10.38 37.55,9.88 36.99,9.88 36.99,9.37 37.55,9.37 37.55,8.88 37.35,8.67 35.72,8.67 35.49,8.44 35.38,8.44 35.15,8.21 33.9,8.21 33.87,8.25 33.87,8.43 33.89,8.46 34.73,8.46 35.31,9.04 35.31,10.13 35.72,10.53 37.4,10.53
N18116330 on BOTTOM (solid shape): 193.5,17.65 193.5,14.89 193.31,14.7 191.71,14.7 191.45,14.97 191.45,17.54 191.75,17.84 193.31,17.84
N19871378 on TOP (solid shape): 19.98,89.45 19.98,88.31 19.67,88 17.76,88 17.63,88.12 17.63,89.44 17.85,89.65 19.78,89.65
N25469058 on TOP (solid shape): 18.01,64.41 18.01,62.02 18.29,61.74 18.29,59.16 17.96,58.83 17.96,57.16 18.23,56.9 18.23,56.22 17.88,55.87 16.66,55.87 16.41,56.12 16.41,64.16 16.85,64.61 17.82,64.61
N26736976 on TOP (solid shape): 149.9,88.82 149.94,88.78 150.22,88.5 152.7,88.5 153.4,87.81 153.4,85.2 153.08,84.88 151.05,84.88 148.24,87.7 148.24,88.37 148.69,88.82
N26737023 on TOP (solid shape): 149.21,86.22 149.21,85.2 148.83,84.82 145.71,84.82 145.4,85.14 145.4,86.28 145.65,86.54 148.89,86.54
N35039154 on BOTTOM (solid shape): 98.92,166.22 98.92,166.22 98.92,165.46 98.99,165.46 98.99,165.12 98.92,164.9 98.91,164.89 97.53,160.98 97.33,160.89 97.01,160.89 96.1,161.23 95.99,161.44 95.95,161.67 97.29,166 97.81,166.42 98.72,166.42
N38004471 on TOP (solid shape): 144.42,148.74 144.42,147.69 144.57,147.54 144.76,147.54 144.83,147.53 144.9,147.54 145.65,147.54 145.71,147.53 145.78,147.54 146.2,147.54 146.33,147.67 147.68,147.67 147.82,147.54 147.82,146.95 147.73,146.87 146.69,146.87 146.43,146.98 146.18,146.87 145.88,146.87 145.62,146.98 145.37,146.87 145.17,146.87 144.92,146.98 144.67,146.87 144.44,146.87 144.44,146.86 143.82,146.86 143.64,147.04 143.64,148.71 143.77,148.84 144.32,148.84

Small or netless copper shapes (teardrops, artwork), in the pictures only: 11 on TOP, 143 on BOTTOM

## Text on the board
User.Comments: VIWGQ/GS | LA9641P | kerry | 2013-04-29 | 2014-04-29 | 1.0
BODY_CENTER: FIGURE | SIZE | 8.0 | 10.0 | 20.0 | 24.0 | 28.0 | 35.0 | 39.0 | 83.0 | 91.0 | 110.0 | 130.0 | 150.0 | 43.0 | 47.0 | 63.0 | 118.0 | 47.0x24.0 | 63.0x35.0 | 75.0x31.0 | 94.0x28.0 | 98.0x24.0 | 98.0x39.0 | 102.0x31.0 | 138.0x98.0 | DRILL CHART: TOP to BOTTOM | ALL UNITS ARE IN MILS | PLATED | NON-PLATED | QTY | 4854 | 1003 | 19 | 8 | 40 | 4 | 2 | 6 | 3 | 7 | 1
User.23: 0.00 | 6.46 | 16.50 | 21.98 | 22.35 | 32.49 | 42.67 | 51.90 | 71.65 | 77.56 | 79.06 | 90.00 | 104.50 | 124.55 | 127.65 | 152.05 | 161.20 | 170.00 | 171.40 | 173.20 | 174.80 | 207.50 | 184.50 | 107.69 | 105.91 | 97.90 | 91.16 | 82.00 | 79.28 | 75.60 | 57.95 | 55.48 | 55.07 | 45.07 | 40.96 | 34.55 | 26.53 | 23.58 | 23.30 | 15.00 | 3.80 | 3.60 | 1.50
User.24: 0.00 | 6.46 | 22.35 | 33.55 | 42.67 | 53.50 | 174.80 | 207.50 | 97.90 | 79.28 | 71.15 | 64.51 | 57.95
User.25: TOP LIMIT
User.26: BTM LIMIT
User.27: 8.00 | dia | 3.80 | 3.00 | 3.30 | 2.80 | 2.10 | 7.00 | 7.50 | 7.75 | 3.50 | R | 4.00 | 6.80 | 6.00 | E | A | B | C | TOP HOLE
User.28: 8.00 | dia | 6.00 | 3.80 | F | G | BTM HOLE
User.29: TOP WHITE
User.30: BTM WHITE
User.32: 0.00 | 6.46 | 16.50 | 21.98 | 22.35 | 28.49 | 42.67 | 51.90 | 71.65 | 77.56 | 79.06 | 90.00 | 104.50 | 124.55 | 127.65 | 152.05 | 161.20 | 170.00 | 171.40 | 173.20 | 174.80 | 207.50 | 184.50 | 107.69 | 105.91 | 97.90 | 91.16 | 82.00 | 79.28 | 75.60 | 57.95 | 55.48 | 55.07 | 45.07 | 40.96 | 34.55 | 26.53 | 23.58 | 23.30 | 15.00 | 3.80 | 3.60 | 1.50
User.33: 0.00 | 6.46 | 22.35 | 33.55 | 42.67 | 53.50 | 174.80 | 207.50 | 97.90 | 79.28 | 71.15 | 64.51 | 57.95
User.34: TOP LIMIT
User.35: BTM LIMIT
User.36: 8.00 | dia | 3.80 | 3.00 | 3.30 | 2.80 | 2.10 | 7.00 | 7.50 | 7.75 | 3.50 | R | 4.00 | 6.80 | 6.00 | E | A | B | C
User.37: 8.00 | dia | 6.00 | 3.80 | F | G
